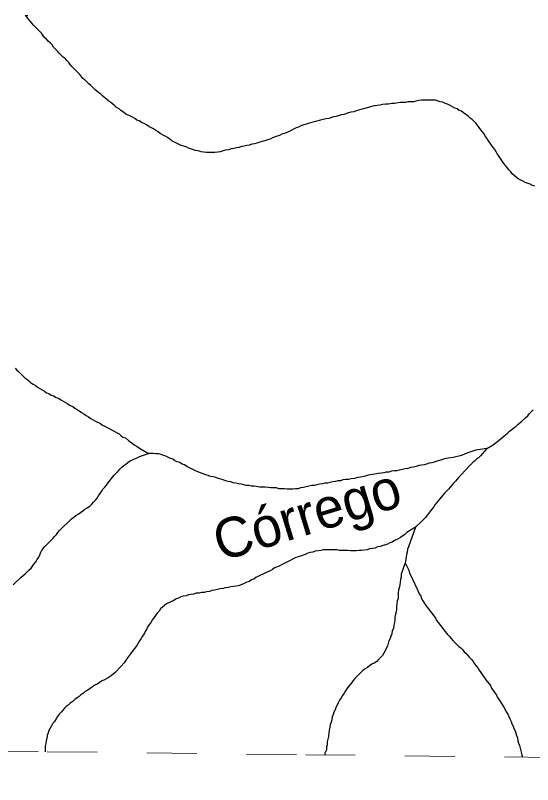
# Model space of a CAD drawing. Extents: x 652.3 to 678, y 7316.9 to 7344.9.
# Drawn here: x 661.032 to 662.07, y 7317.076 to 7318.621 of the extents above; entities that cross this region are included whole.
import ezdxf
from ezdxf.enums import TextEntityAlignment as Align

# ---------------------------------------------------------------- set-up
doc = ezdxf.new("R2010")
doc.units = 0
doc.header["$LTSCALE"] = 0.032
doc.linetypes.add('SHORT_DASHED', pattern=[2.7, 1.5, -1.2])
doc.layers.add('53', color=7, linetype='SHORT_DASHED', lineweight=13)
doc.layers.add('7', color=7, linetype='Continuous', lineweight=25)
doc.layers.add('61', color=7, linetype='Continuous')

msp = doc.modelspace()

# ---------------------------------------------------------------- linework, layer by layer
at = {"layer": '53'}
msp.add_lwpolyline([(657.4691, 7317.1832), (657.9871, 7317.1774), (658.5052, 7317.1717), (659.0233, 7317.1658), (659.5414, 7317.16), (660.0594, 7317.1542), (660.5775, 7317.1483), (661.0956, 7317.1424), (661.6137, 7317.1365), (662.1318, 7317.1306), (662.6498, 7317.1247), (663.1679, 7317.1187), (663.686, 7317.1127), (664.2041, 7317.1067), (664.7222, 7317.1007), (665.2403, 7317.0947), (665.7584, 7317.0886), (666.2765, 7317.0825), (666.7945, 7317.0764)], dxfattribs=at)
at = {"layer": '7'}
for p, q in [((661.6529, 7317.1389), (661.6525, 7317.1361)), ((662.0482, 7317.1355), (662.0496, 7317.1315))]:
    msp.add_line(p, q, dxfattribs=at)
for points in [[(661.1163, 7318.549), (661.1084, 7318.5569), (661.1052, 7318.5617), (661.1012, 7318.5657), (661.0972, 7318.5689), (661.0941, 7318.5728), (661.0901, 7318.576), (661.0869, 7318.5808), (661.0837, 7318.5848), (661.0678, 7318.6007), (661.0646, 7318.6047), (661.0551, 7318.6166), (661.0511, 7318.6206), (661.0567, 7318.6206)], [(661.7004, 7318.4248), (661.6908, 7318.4216), (661.6853, 7318.4209), (661.6757, 7318.4177), (661.6701, 7318.4169), (661.6606, 7318.4137), (661.655, 7318.4129), (661.6494, 7318.4113), (661.6439, 7318.4105), (661.6343, 7318.4073), (661.6288, 7318.4065), (661.624, 7318.4049), (661.6192, 7318.4033), (661.6049, 7318.3986), (661.6001, 7318.3962), (661.5953, 7318.3946), (661.581, 7318.3874), (661.5762, 7318.3858), (661.5715, 7318.3835), (661.5667, 7318.3819), (661.5619, 7318.3795), (661.5571, 7318.3779), (661.5476, 7318.3747), (661.5428, 7318.3723), (661.5381, 7318.3707), (661.5325, 7318.3691), (661.5269, 7318.3675), (661.5221, 7318.3659), (661.5166, 7318.3644), (661.5118, 7318.3628), (661.5062, 7318.362), (661.5014, 7318.3604), (661.4959, 7318.3596), (661.4911, 7318.358), (661.4855, 7318.3572), (661.4808, 7318.3556), (661.4752, 7318.3548), (661.4704, 7318.3532), (661.4648, 7318.3524), (661.4593, 7318.3508), (661.4537, 7318.35), (661.4489, 7318.3484), (661.4434, 7318.3469), (661.4378, 7318.3461), (661.4322, 7318.3453), (661.4155, 7318.3453), (661.4099, 7318.3461), (661.4044, 7318.3469), (661.3988, 7318.3484), (661.3932, 7318.3492), (661.3837, 7318.3524), (661.3789, 7318.354), (661.3741, 7318.3564), (661.3646, 7318.3596), (661.3455, 7318.3691), (661.3415, 7318.3723), (661.3367, 7318.3755), (661.332, 7318.3779), (661.3272, 7318.3811), (661.3224, 7318.3835), (661.3184, 7318.3866), (661.3137, 7318.3898), (661.3089, 7318.393), (661.2993, 7318.3978), (661.2946, 7318.401), (661.2898, 7318.4033), (661.285, 7318.4057), (661.2802, 7318.4089), (661.2755, 7318.4105), (661.2715, 7318.4137), (661.2667, 7318.4161), (661.2524, 7318.4232), (661.2484, 7318.4264), (661.2436, 7318.4296), (661.2397, 7318.4328), (661.2349, 7318.436), (661.2309, 7318.4392), (661.2269, 7318.4423), (661.223, 7318.4455), (661.219, 7318.4487), (661.215, 7318.4519), (661.211, 7318.4551), (661.207, 7318.4582), (661.2031, 7318.4622), (661.1991, 7318.4654), (661.1951, 7318.4686), (661.1911, 7318.4718), (661.1832, 7318.4797), (661.1792, 7318.4829), (661.1712, 7318.4909), (661.1673, 7318.4941), (661.1609, 7318.502), (661.145, 7318.5179), (661.1418, 7318.5219), (661.1386, 7318.5259), (661.1346, 7318.5299), (661.1315, 7318.5338), (661.1275, 7318.537), (661.1235, 7318.541), (661.1195, 7318.545), (661.1163, 7318.549)], [(662.0743, 7318.2776), (662.0696, 7318.2792), (662.0648, 7318.2816), (662.0552, 7318.2848), (662.0505, 7318.288), (662.0409, 7318.2927), (662.0369, 7318.2959), (662.033, 7318.2991), (662.029, 7318.3023), (662.0258, 7318.3063), (662.0218, 7318.3103), (662.0186, 7318.315), (662.0123, 7318.323), (662.0027, 7318.3373), (661.9995, 7318.3421), (661.9964, 7318.3469), (661.994, 7318.3516), (661.9908, 7318.3556), (661.9876, 7318.3604), (661.9844, 7318.3644), (661.9812, 7318.3691), (661.9781, 7318.3739), (661.9749, 7318.3779), (661.9725, 7318.3827), (661.9661, 7318.3906), (661.9629, 7318.3954), (661.9566, 7318.4033), (661.9526, 7318.4073), (661.9486, 7318.4113), (661.9446, 7318.4145), (661.9407, 7318.4185), (661.9359, 7318.4216), (661.9311, 7318.4248), (661.9271, 7318.428), (661.9224, 7318.4296), (661.9184, 7318.4328), (661.9136, 7318.4344), (661.9088, 7318.4368), (661.9041, 7318.4399), (661.8993, 7318.4423), (661.8945, 7318.4439), (661.8897, 7318.4463), (661.8842, 7318.4471), (661.8746, 7318.4503), (661.8468, 7318.4503), (661.8412, 7318.4495), (661.8356, 7318.4487), (661.8309, 7318.4471), (661.8197, 7318.4471), (661.815, 7318.4455), (661.8038, 7318.4455), (661.7927, 7318.4439), (661.7871, 7318.4439), (661.7807, 7318.4423), (661.7752, 7318.4423), (661.7688, 7318.4415), (661.7632, 7318.4407), (661.7577, 7318.4399), (661.7521, 7318.4392), (661.7473, 7318.4376), (661.7306, 7318.4328), (661.725, 7318.432), (661.7203, 7318.4304), (661.7155, 7318.4288), (661.7107, 7318.4272), (661.7051, 7318.4264), (661.7004, 7318.4248)], [(661.0312, 7317.9124), (661.0344, 7317.9084), (661.0384, 7317.9052), (661.0503, 7317.8933), (661.0543, 7317.8901), (661.0583, 7317.8869), (661.0622, 7317.8838), (661.067, 7317.8806), (661.0718, 7317.8774), (661.0758, 7317.8742), (661.0805, 7317.8718), (661.0853, 7317.8686), (661.0901, 7317.8663), (661.0941, 7317.8631), (661.0988, 7317.8615), (661.1036, 7317.8583), (661.1084, 7317.8567), (661.1132, 7317.8535), (661.1179, 7317.8519), (661.1227, 7317.8488), (661.1275, 7317.8464), (661.1322, 7317.8432), (661.137, 7317.8408), (661.1418, 7317.8376), (661.1466, 7317.8352), (661.1506, 7317.832), (661.1553, 7317.8297), (661.1593, 7317.8265), (661.1641, 7317.8233), (661.1689, 7317.8209), (661.1736, 7317.8177), (661.1784, 7317.8145), (661.1832, 7317.8114), (661.1879, 7317.809), (661.1927, 7317.8058), (661.2023, 7317.801), (661.2062, 7317.7978), (661.211, 7317.7962), (661.2158, 7317.7931), (661.2301, 7317.7859), (661.2349, 7317.7835), (661.2397, 7317.7803), (661.2436, 7317.7771), (661.2476, 7317.774), (661.2524, 7317.7724), (661.2596, 7317.7668), (661.2667, 7317.7612), (661.2715, 7317.758), (661.2763, 7317.7549), (661.281, 7317.7517), (661.2985, 7317.7413)], [(661.9781, 7317.7509), (661.9908, 7317.7588), (661.9948, 7317.762), (661.9995, 7317.7652), (662.0035, 7317.7684), (662.0075, 7317.7716), (662.0115, 7317.7755), (662.0155, 7317.7787), (662.0194, 7317.7819), (662.0234, 7317.7859), (662.0282, 7317.7891), (662.0322, 7317.7923), (662.0362, 7317.7954), (662.0401, 7317.7994), (662.0441, 7317.8026), (662.0481, 7317.8058), (662.056, 7317.8137), (662.06, 7317.8169), (662.0632, 7317.8209), (662.0712, 7317.8289)], [(661.9781, 7317.7509), (661.9558, 7317.7477), (661.9415, 7317.7429), (661.9367, 7317.7413), (661.9319, 7317.7389), (661.9263, 7317.7374), (661.9216, 7317.7358), (661.916, 7317.7342), (661.9104, 7317.7334), (661.9001, 7317.7318), (661.8921, 7317.7302), (661.8874, 7317.7286), (661.8778, 7317.7254), (661.8722, 7317.7238), (661.8675, 7317.7222), (661.8619, 7317.7214), (661.8571, 7317.7199), (661.8523, 7317.7183), (661.8468, 7317.7175), (661.8412, 7317.7167), (661.8364, 7317.7151), (661.8309, 7317.7135), (661.8253, 7317.7127), (661.8197, 7317.7111), (661.8142, 7317.7103), (661.8086, 7317.7087), (661.8022, 7317.7079), (661.7974, 7317.7063), (661.7919, 7317.7063), (661.7863, 7317.7055), (661.7815, 7317.7039), (661.776, 7317.7039), (661.7712, 7317.7023), (661.7656, 7317.7015), (661.76, 7317.7008), (661.7489, 7317.6992), (661.7433, 7317.6984), (661.7378, 7317.6968), (661.7314, 7317.6952), (661.7242, 7317.6936), (661.7187, 7317.6928), (661.7123, 7317.6912), (661.7059, 7317.6904), (661.7004, 7317.6888), (661.6948, 7317.6888), (661.6892, 7317.688), (661.6845, 7317.6864), (661.6789, 7317.6864), (661.6741, 7317.6848), (661.6685, 7317.684), (661.663, 7317.6832), (661.6582, 7317.6817), (661.6526, 7317.6817), (661.6479, 7317.6801), (661.6423, 7317.6793), (661.6367, 7317.6785), (661.6319, 7317.6769), (661.6264, 7317.6769), (661.6208, 7317.6753), (661.6152, 7317.6745), (661.6097, 7317.6729), (661.6041, 7317.6721), (661.5993, 7317.6705), (661.5937, 7317.6705), (661.5882, 7317.6697), (661.577, 7317.6697), (661.5715, 7317.6705), (661.5603, 7317.6705), (661.5556, 7317.6721), (661.5444, 7317.6721), (661.5388, 7317.6729), (661.5333, 7317.6737), (661.5221, 7317.6737), (661.511, 7317.6753), (661.5054, 7317.6753), (661.5007, 7317.6769), (661.4951, 7317.6769), (661.4903, 7317.6785), (661.4847, 7317.6793), (661.4792, 7317.6801), (661.4744, 7317.6817), (661.4688, 7317.6825), (661.4641, 7317.684), (661.4585, 7317.6848), (661.4537, 7317.6864), (661.4489, 7317.688), (661.4394, 7317.6912), (661.4338, 7317.6928), (661.429, 7317.6944), (661.4235, 7317.6952), (661.4187, 7317.6968), (661.4139, 7317.6984), (661.4044, 7317.7015), (661.3996, 7317.7039), (661.3948, 7317.7055), (661.3757, 7317.7151), (661.371, 7317.7183), (661.3662, 7317.7199), (661.3614, 7317.723), (661.3566, 7317.7246), (661.3519, 7317.7262)], [(661.9781, 7317.7509), (661.9653, 7317.7366), (661.9614, 7317.7326), (661.9574, 7317.7294), (661.9534, 7317.7254), (661.9494, 7317.7222), (661.9454, 7317.7183), (661.9415, 7317.7151), (661.9351, 7317.7079), (661.9256, 7317.6976), (661.9216, 7317.6936), (661.9152, 7317.6856), (661.9112, 7317.6817), (661.908, 7317.6777), (661.9041, 7317.6737), (661.9009, 7317.6697), (661.8929, 7317.6618), (661.8834, 7317.6498), (661.8802, 7317.6459), (661.8738, 7317.6379), (661.8706, 7317.6331), (661.8579, 7317.6172), (661.8547, 7317.6124), (661.8468, 7317.6045), (661.8348, 7317.5933)], [(661.0272, 7317.4772), (661.0431, 7317.4931), (661.0471, 7317.4963), (661.0511, 7317.4994), (661.0551, 7317.5034), (661.059, 7317.5074), (661.063, 7317.5106), (661.0662, 7317.5146), (661.0694, 7317.5193), (661.0726, 7317.5233), (661.075, 7317.5281), (661.0781, 7317.5321), (661.0805, 7317.5368), (661.0821, 7317.5416), (661.0845, 7317.5464), (661.0877, 7317.5504), (661.0909, 7317.5543), (661.1068, 7317.5703), (661.11, 7317.5742), (661.1139, 7317.5782), (661.1171, 7317.5822), (661.1203, 7317.5862), (661.1442, 7317.61), (661.149, 7317.6132), (661.1529, 7317.6164), (661.1577, 7317.6196), (661.1625, 7317.6228), (661.1673, 7317.626), (661.1712, 7317.6291), (661.176, 7317.6323), (661.1808, 7317.6355), (661.1848, 7317.6395), (661.1887, 7317.6435), (661.1927, 7317.6474), (661.1959, 7317.6514), (661.1983, 7317.6562), (661.2015, 7317.661), (661.2047, 7317.6649), (661.207, 7317.6697), (661.211, 7317.6737), (661.2142, 7317.6777), (661.2174, 7317.6817), (661.2301, 7317.6976), (661.2381, 7317.7055), (661.2413, 7317.7095), (661.2452, 7317.7135), (661.2492, 7317.7167), (661.2532, 7317.7199), (661.2572, 7317.723), (661.2619, 7317.7262), (661.2691, 7317.7294), (661.2763, 7317.7326), (661.281, 7317.735), (661.2985, 7317.7413)], [(661.3519, 7317.7262), (661.3479, 7317.7294), (661.3431, 7317.731), (661.3336, 7317.7358), (661.3288, 7317.7374), (661.324, 7317.7389), (661.3192, 7317.7405), (661.3137, 7317.7405), (661.3081, 7317.7413), (661.2985, 7317.7413)], [(661.8348, 7317.5933), (661.8173, 7317.5822), (661.8134, 7317.5782), (661.8046, 7317.5726), (661.7974, 7317.5687), (661.7927, 7317.5663), (661.7879, 7317.5631), (661.7831, 7317.5615), (661.7783, 7317.5591), (661.764, 7317.5543), (661.7585, 7317.5536), (661.7537, 7317.5512), (661.7481, 7317.5504), (661.7425, 7317.5496), (661.7378, 7317.548), (661.7266, 7317.5464), (661.7211, 7317.5464), (661.7155, 7317.5456), (661.7043, 7317.5456), (661.6988, 7317.5464), (661.6821, 7317.5464), (661.6773, 7317.548), (661.6494, 7317.548), (661.6447, 7317.5464), (661.6391, 7317.5456), (661.6335, 7317.5448), (661.6288, 7317.5432), (661.6232, 7317.5424), (661.6184, 7317.5408), (661.6136, 7317.5384), (661.6041, 7317.5353), (661.5993, 7317.5337), (661.5945, 7317.5321), (661.5802, 7317.5249), (661.5754, 7317.5225), (661.5659, 7317.5177), (661.5611, 7317.5146), (661.5516, 7317.5114), (661.5476, 7317.5082), (661.5428, 7317.5058), (661.5381, 7317.5034), (661.5285, 7317.4986), (661.5237, 7317.4971), (661.5142, 7317.4923), (661.5102, 7317.4891), (661.5054, 7317.4875), (661.5007, 7317.4843), (661.4959, 7317.4827), (661.4911, 7317.4803), (661.4863, 7317.478), (661.4816, 7317.4764), (661.4752, 7317.4748), (661.4696, 7317.474), (661.4641, 7317.4732), (661.4585, 7317.4724), (661.4529, 7317.4716), (661.4481, 7317.47), (661.4426, 7317.4692), (661.437, 7317.4684), (661.4314, 7317.4668), (661.4259, 7317.466), (661.4211, 7317.4644), (661.4155, 7317.4636), (661.4107, 7317.462), (661.4052, 7317.462), (661.4004, 7317.4605), (661.3948, 7317.4605), (661.3901, 7317.4589), (661.3789, 7317.4573), (661.3741, 7317.4557), (661.3686, 7317.4549), (661.3638, 7317.4533), (661.359, 7317.4509), (661.3542, 7317.4493), (661.3495, 7317.4461), (661.3447, 7317.4437), (661.3351, 7317.439), (661.3312, 7317.4358), (661.3272, 7317.4326), (661.3232, 7317.4294), (661.32, 7317.4247), (661.3161, 7317.4207), (661.3129, 7317.4159), (661.3097, 7317.4111), (661.3065, 7317.4071), (661.3041, 7317.4024), (661.3009, 7317.3984), (661.2978, 7317.3936), (661.2954, 7317.3888), (661.2922, 7317.3841), (661.2898, 7317.3793), (661.2866, 7317.3745), (661.2842, 7317.3697), (661.281, 7317.365), (661.2779, 7317.3602), (661.2755, 7317.3554), (661.2659, 7317.3435), (661.2627, 7317.3387), (661.2564, 7317.3308), (661.25, 7317.3212), (661.2436, 7317.3133)], [(661.8348, 7317.5933), (661.8205, 7317.5536), (661.8189, 7317.5488), (661.8181, 7317.5432), (661.8165, 7317.5384), (661.8157, 7317.5329), (661.8142, 7317.5217)], [(661.8142, 7317.5217), (661.8062, 7317.4986), (661.8062, 7317.4931), (661.8046, 7317.4883), (661.8038, 7317.4827), (661.803, 7317.4772), (661.8022, 7317.4716), (661.8006, 7317.4668), (661.7998, 7317.4613), (661.7998, 7317.4557), (661.7998, 7317.4501), (661.7982, 7317.4453), (661.7974, 7317.4398), (661.7966, 7317.4342), (661.7966, 7317.4286), (661.7959, 7317.4231), (661.7943, 7317.4183), (661.7935, 7317.4127), (661.7935, 7317.4071), (661.7927, 7317.4016), (661.7911, 7317.3968), (661.7903, 7317.3896), (661.7879, 7317.3849), (661.7871, 7317.3793), (661.7855, 7317.3745), (661.7839, 7317.3697), (661.7815, 7317.365), (661.7799, 7317.3594), (661.7783, 7317.3546), (661.776, 7317.3499), (661.7736, 7317.3451), (661.7712, 7317.3403), (661.7688, 7317.3355), (661.7648, 7317.3316), (661.7608, 7317.3276), (661.7569, 7317.3236), (661.7521, 7317.3204), (661.7473, 7317.318), (661.7425, 7317.3148), (661.7386, 7317.3117), (661.7338, 7317.3085), (661.729, 7317.3053), (661.725, 7317.3013), (661.7211, 7317.2973), (661.7171, 7317.2934), (661.7131, 7317.2894), (661.7099, 7317.2854), (661.7067, 7317.2814), (661.7036, 7317.2774), (661.7004, 7317.2735), (661.6972, 7317.2687), (661.694, 7317.2647), (661.6916, 7317.2599), (661.6884, 7317.2552), (661.6853, 7317.2504), (661.6821, 7317.2456), (661.6797, 7317.2408), (661.6773, 7317.2361), (661.6749, 7317.2313), (661.6733, 7317.2265), (661.6709, 7317.2217), (661.6693, 7317.217), (661.6677, 7317.2122), (661.667, 7317.2066), (661.6654, 7317.2019), (661.6638, 7317.1971), (661.663, 7317.1915), (661.6614, 7317.1859), (661.6606, 7317.1804), (661.6598, 7317.1732), (661.659, 7317.1676), (661.6574, 7317.1621), (661.6574, 7317.1565), (661.6558, 7317.1517), (661.6558, 7317.1462), (661.6542, 7317.1422), (661.6536, 7317.1407), (661.653, 7317.1392), (661.6529, 7317.1389)], [(661.8142, 7317.5217), (661.8213, 7317.5066), (661.8229, 7317.501), (661.8253, 7317.4963), (661.8285, 7317.4891), (661.8333, 7317.4788), (661.8356, 7317.474), (661.838, 7317.4692), (661.8404, 7317.4644), (661.842, 7317.4597), (661.8452, 7317.4549), (661.8468, 7317.4501), (661.8492, 7317.4453), (661.8555, 7317.4358), (661.8587, 7317.4318), (661.8619, 7317.427), (661.8714, 7317.4151), (661.8746, 7317.4103), (661.877, 7317.4056), (661.8802, 7317.4016), (661.8993, 7317.3777), (661.9033, 7317.3737), (661.9065, 7317.3697), (661.9096, 7317.3658), (661.9216, 7317.3538), (661.9256, 7317.3507), (661.9295, 7317.3467), (661.9327, 7317.3427), (661.9367, 7317.3395), (661.9399, 7317.3355), (661.9431, 7317.3316), (661.947, 7317.3276), (661.9502, 7317.3236), (661.9534, 7317.3188), (661.9598, 7317.3109), (661.9629, 7317.3061), (661.9661, 7317.3013), (661.9757, 7317.287), (661.9852, 7317.2751), (661.9876, 7317.2703), (661.9908, 7317.2655), (661.9972, 7317.256), (661.9995, 7317.2512), (662.0027, 7317.2464), (662.0123, 7317.2321), (662.0147, 7317.2273), (662.0171, 7317.2225), (662.0202, 7317.2178), (662.0218, 7317.213), (662.0242, 7317.2082), (662.0266, 7317.2034), (662.0282, 7317.1987), (662.0306, 7317.1939), (662.0322, 7317.1891), (662.0346, 7317.1844), (662.0377, 7317.1748), (662.0393, 7317.17), (662.0401, 7317.1645), (662.0417, 7317.1597), (662.0433, 7317.1549), (662.0473, 7317.139), (662.0481, 7317.1359), (662.0482, 7317.1355)], [(661.2436, 7317.3133), (661.2317, 7317.3013), (661.2277, 7317.2981), (661.2238, 7317.295), (661.2198, 7317.2918), (661.2102, 7317.287), (661.2055, 7317.2846), (661.2007, 7317.2814), (661.1959, 7317.2782), (661.1911, 7317.2759), (661.1864, 7317.2727), (661.1816, 7317.2695), (661.1768, 7317.2663), (661.172, 7317.2631), (661.1681, 7317.2599), (661.1633, 7317.2568), (661.1593, 7317.2536), (661.1553, 7317.2504), (661.1506, 7317.2472), (661.1466, 7317.2432), (661.1418, 7317.2401), (661.1378, 7317.2361), (661.1338, 7317.2329), (661.1299, 7317.2297), (661.1235, 7317.2217), (661.1195, 7317.2178), (661.1163, 7317.213), (661.1132, 7317.2082), (661.11, 7317.2034), (661.1068, 7317.1995), (661.1044, 7317.1947), (661.1012, 7317.1899), (661.0988, 7317.1851), (661.0972, 7317.1804), (661.0956, 7317.1748), (661.0949, 7317.1692), (661.0933, 7317.1645), (661.0925, 7317.1589), (661.0917, 7317.1533), (661.0917, 7317.147), (661.0917, 7317.1424)]]:
    msp.add_lwpolyline(points, dxfattribs=at)

# ---------------------------------------------------------------- texts
at = {"layer": '61'}
msp.add_text('Córrego', height=0.08, rotation=17.078, dxfattribs=at).set_placement((661.6285, 7317.5806), align=Align.CENTER)

doc.saveas('drawing.dxf')
